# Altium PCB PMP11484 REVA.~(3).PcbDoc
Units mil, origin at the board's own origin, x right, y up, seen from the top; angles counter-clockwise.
Board outline 4950 x 3450 mil, 2 copper layers (Top Layer, Bottom Layer), stack 62 mil thick; 51 components, 24 nets, 109 pads, 5 vias.
Unrouted connection lines stored in the file: 85.
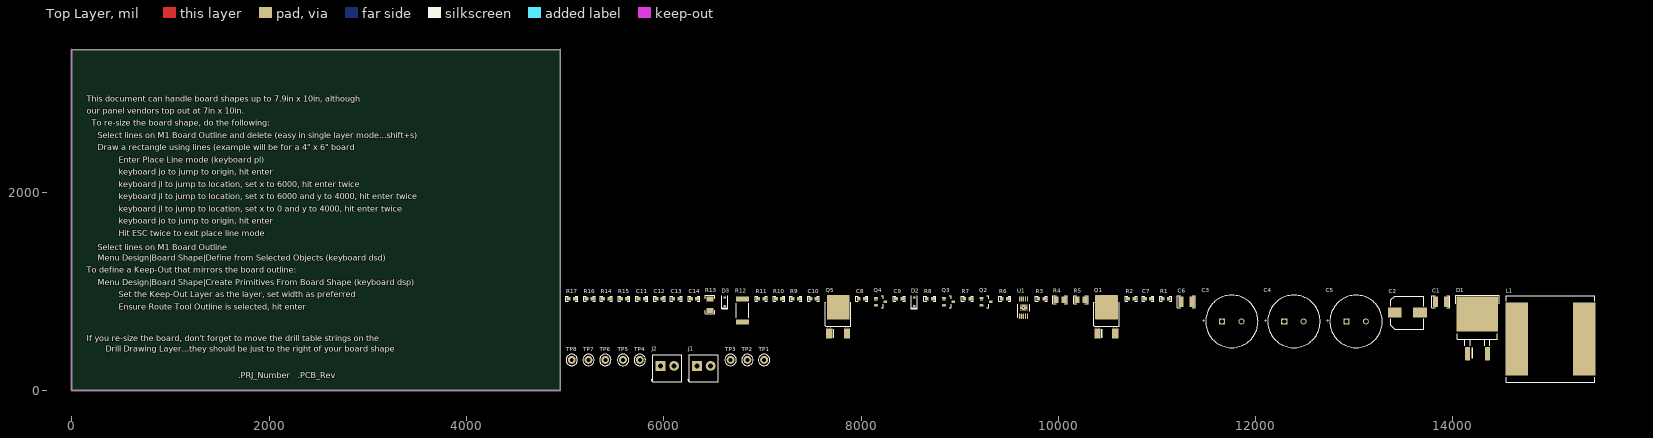
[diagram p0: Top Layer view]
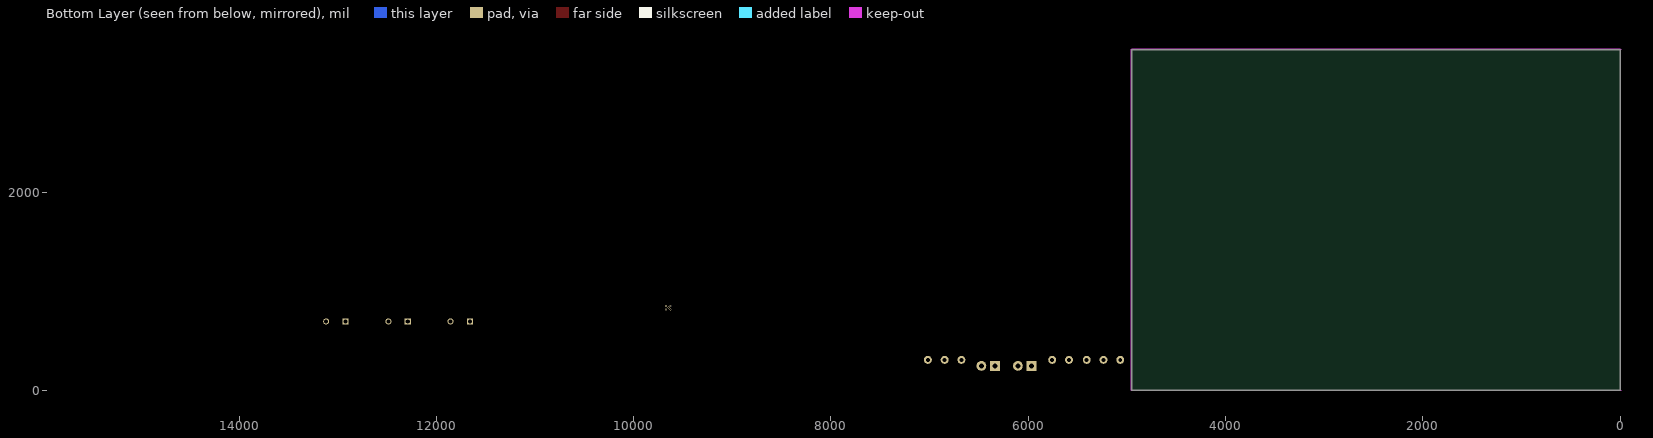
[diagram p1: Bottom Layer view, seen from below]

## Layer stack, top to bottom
Top Solder: solder mask 0.4, Solder Resist, Dk 3.5
Top Layer: signal copper 1.4
Dielectric1: core 59.2, FR-4, Dk 4.8
Bottom Layer: signal copper 1.4
Bottom Solder: solder mask 0.4, Solder Resist, Dk 3.5

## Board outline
0,0 4950,0 4950,3450 0,3450

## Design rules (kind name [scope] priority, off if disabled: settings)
AcuteAngle [All] p1: minimum=4.50000000000000E+0001 checktracksonly=FALSE
AssemblyTestPointUsage [All] p1: valid=2
Clearance Clearance_Keepouts [((IsTrack Or IsArc) And Not InPoly) And IsFree and IsKeepOut vs ((IsTrack Or IsArc) And Not InPoly) And IsFree and IsKeepOut] p1: gap=0
Clearance Clearance_BoardEdge_MountingHoles [OnCopper and InComponentClass('Mounting Holes') vs IsKeepOut] p2: gap=40
Clearance Clearance_BoardEdge_Poly [OnCopper and InPoly vs IsKeepOut] p3: gap=25
Clearance Clearance_BoardEdge [OnCopper and Not InComponentClass('Logo') and not InComponentClass('FiducialMark') and not InRegion(1000,500,4000,800) and Not IsKeepout vs IsKeepOut] p4: gap=75
Clearance Clearance_Poly [InPolygon] p5: gap=25
Clearance [All] p6: gap=7.87
ComponentClearance ComponentClearance_MountingHoles_FiducialMarks [InComponentClass('Mounting Holes') vs InComponentClass('FiducialMark')] p1: gap=50 collisioncheckmode=3 verticalgap=10 showdistances=FALSE
ComponentClearance ComponentClearance_Shunt [InComponentClass('Header') vs InComponentClass('Shunt')] p2: gap=0 collisioncheckmode=3 verticalgap=0 showdistances=FALSE
ComponentClearance ComponentClearance_Logo [InComponentClass('Logo')] p3: gap=50 collisioncheckmode=3 verticalgap=10 showdistances=FALSE
ComponentClearance ComponentClearance_ScrewToNut [(HasFootprint('NY PMS 440 0025 PH')) vs (HasFootprint('Keystone_1902C'))] p4: gap=5 collisioncheckmode=3 verticalgap=10 showdistances=FALSE
ComponentClearance ComponentClearance_MountingHoles [InComponentClass('Mounting Holes')] p5: gap=250 collisioncheckmode=3 verticalgap=100000 showdistances=FALSE
ComponentClearance ComponentClearance_SmallPassives [HasFootprint('0201*') or HasFootprint('0402*') or HasFootprint('0508') or HasFootprint('0603*') or HasFootprint('0612') or HasFootprint('0805*') or HasFootprint('0815*') or HasFootprint('0830*') or HasFootprint('1206*') or HasFootprint('1210*') or HasFootprint('1808*') or HasFootprint('1812*') or HasFootprint('1825*') or HasFootprint('2010*') or HasFootprint('2220*') or HasFootprint('2225*') or HasFootprint('2512*') or HasFootprint('2728*') or HasFootprint('3518*') vs HasFootprint('0201*') or HasFootprint('0402*') or HasFootprint('0508') or HasFootprint('0603*') or HasFootprint('0612') or HasFootprint('0805*') or HasFootprint('0815*') or HasFootprint('0830*') or HasFootprint('1206*') or HasFootprint('1210*') or HasFootprint('1808*') or HasFootprint('1812*') or HasFootprint('1825*') or HasFootprint('2010*') or HasFootprint('2220*') or HasFootprint('2225*') or HasFootprint('2512*') or HasFootprint('2728*') or HasFootprint('3518*')] p6: gap=20 collisioncheckmode=3 verticalgap=10 showdistances=FALSE
ComponentClearance ComponentClearance_THtoSMT [IsThruComponent vs IsSMTComponent] p7: gap=100 collisioncheckmode=3 verticalgap=30 showdistances=FALSE
ComponentClearance ComponentClearance_THtoTH [IsThruComponent vs IsThruComponent] p8: gap=118.11 collisioncheckmode=3 verticalgap=30 showdistances=FALSE
ComponentClearance [All] p9: gap=40 collisioncheckmode=3 verticalgap=10 showdistances=FALSE
DiffPairsRouting [All] p1: maxlimit=100 minlimit=10 mostfreqgap=10 toplayer_minwidth=15 toplayer_maxwidth=15 toplayer_prefwidth=15 bottomlayer_minwidth=15 bottomlayer_maxwidth=15 bottomlayer_prefwidth=15 maxuncoupledlength=1000
FabricationTestPointUsage TestPointUsage [All] p1: valid=2 allowmultiple=FALSE
FabricationTestpoint Testpoint [All] p1: side=3 testpointundercomponent=TRUE minsize=40 maxsize=100 preferedsize=60 minholesize=0 maxholesize=40 preferedholesize=32 testpointgrid=1 allowsidetop=TRUE allowsidebottom=TRUE usegrid=TRUE gridtolerance=0.01
FanoutControl Fanout_LCC [IsLCC] p1: bgadir=Out bgaviamode=Centered fanoutstyle=Auto fanoutdirection=Alternating viagrid=1 // Fanout_LCC (Default Rule)
FanoutControl Fanout_BGA [IsBGA] p2: bgadir=Out bgaviamode=Centered fanoutstyle=Auto fanoutdirection=Alternating viagrid=1 // Fanout_BGA (Default Rule)
FanoutControl Fanout_Default [All] p4: bgadir=Out bgaviamode=Centered fanoutstyle=Auto fanoutdirection=Alternating viagrid=1 // Fanout_Default (Default Rule)
FanoutControl Fanout_Small [(CompPinCount < 5)] p5: bgadir=Out bgaviamode=Centered fanoutstyle=Auto fanoutdirection=OutThenIn viagrid=1 // Fanout_Small (Default Rule)
HoleSize [All] p1: absolutevalues=TRUE maxlimit=251 minlimit=8 maxpercent=80.000 minpercent=20.000
MinimumAnnularRing MinimumAnnularRing_ThermalPadVias [IsVia and InAnyComponent] p1: minimumring=5.91
MinimumAnnularRing [All] p2: minimumring=9
MinimumSolderMaskSliver MinimumSolderMaskSliver_Logo [InComponentClass('Logo') vs InComponentClass('Logo')] p1: minsoldermaskwidth=0.7
MinimumSolderMaskSliver [All] p2: minsoldermaskwidth=3.94
PlaneConnect [All] p1: planeconnectstyle=Relief reliefexpansion=10 reliefentries=4 reliefconductorwidth=10 reliefairgap=10
PolygonConnect [All] p1: connectstyle=Relief reliefconductorwidth=10 reliefentries=4 polygonreliefangle="90 Angle" airgapwidth=10
RoutingVias ThermalPadVias [IsVia and InAnyComponent] p1: holewidth=7.87 width=19.68 viastyle="Through Hole" minholewidth=7.87 minwidth=19.68 maxholewidth=12.99 maxwidth=23.62
RoutingVias [All] p2: holewidth=16 width=34 viastyle="Through Hole" minholewidth=7.87 minwidth=26 maxholewidth=40 maxwidth=65
SilkToBoardRegionClearance [Not ((IsComment or IsDesignator) And (Hide <> 'False')) and not InRegion(1000,500,4000,800)] p1:
SilkToSilkClearance SilkToSilkClearance_Pb-FreeLogo [(HasFootprint('Pb-Free_Overlay_Medium') OR HasFootprint('Pb-Free_Overlay_Small')) vs (HasFootprint('Pb-Free_Overlay_Medium') OR HasFootprint('Pb-Free_Overlay_Small'))] p1: silktosilkclearance=0
SilkToSilkClearance [All] p2: silktosilkclearance=4
SilkToSolderMaskClearance SilkToComonentPadClearance [IsPad and InAnycomponent] p1: minsilkscreentomaskgap=5 clearancetoexposedcopper=TRUE
SilkToSolderMaskClearance "Silk to Solder Mask Opening" [All] p2: minsilkscreentomaskgap=4 clearancetoexposedcopper=FALSE
SolderMaskExpansion [All] p1: expansion=1.97
UnpouredPolygon [All] p1: allowunpoured=FALSE
Width [All] p1: maxlimit=100 minlimit=6 preferedwidth=10 checkconnectedcopper=TRUE
14 further rules are at their usual default settings.

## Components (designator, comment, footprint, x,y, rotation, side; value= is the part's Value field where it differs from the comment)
C1 "C3225X7R1H475M250AB" 1210 13878,896 r0 top
C2 "EEHZA1H680P" SM_RADIAL_8MM 13538,786 r0 top
C3 "UBT1K221MHD1TO" BT_1250x2500 11758,696 r0 top
C4 "UBT1K221MHD1TO" BT_1250x2500 12388,696 r0 top
C5 "UBT1K221MHD1TO" BT_1250x2500 13018,696 r0 top
C6 "GRM32ER72A225KA35L" 1210 11298,896 r0 top
C7 "C1608X7R1H104K" 0603 10908,926 r0 top
C8 "C1608X7R1H104K" 0603 8008,926 r0 top
C9 "C1608C0G2A102J" 0603 8388,926 r0 top
C10 "C1608C0G1H331J" 0603 7518,926 r0 top
C11 "C1608X7R1H104K" 0603 5778,926 r0 top
C12 "C1608C0G1H331J" 0603 5958,926 r0 top
C13 "C1608X7R1C105K" 0603 6128,926 r0 top
C14 "C1608C0G1H331J" 0603 6308,926 r0 top
D1 "NRVBB1060T4G" DDPAK 14248,616 r90 top
D2 "MMSZ5230BS-7-F" sod-323 8538,896 r90 top
D3 "MMSZ5230BS-7-F" sod-323 6618,896 r90 top
J1 "ED555/2DS" TERM_BLK_ED555-2DS 6338,246 r0 top
J2 "ED555/2DS" TERM_BLK_ED555-2DS 5968,246 r0 top
L1 "IHLP8787MZER220M5A" IHLP8787MZ 14988,516 r0 top
Q1 "IPD50N06S4L-12" DPAK 10488,706 r90 top
Q2 "MMBT2222A" SOT-23 9268,896 r0 top
Q3 "MMBT2222A" SOT-23 8888,896 r0 top
Q4 "MMBT2907A" SOT-23 8198,896 r0 top
Q5 "IPD50N06S4L-12" DPAK 7768,706 r90 top
R1 "CRCW06034R70JNEA" 0603 11088,926 r0 top
R2 "CRCW0603348KFKEA" 0603 10738,926 r0 top
R3 "CRCW0603402KFKEA" 0603 9828,926 r0 top
R4 "CRCW080520K0FKEA" 0805_HV 10018,916 r0 top
R5 "CRCW080520K0FKEA" 0805_HV 10228,916 r0 top
R6 "CRCW06030000Z0EA" 0603 9458,926 r0 top
R7 "CRCW06034R70JNEA" 0603 9078,926 r0 top
R8 "CRCW06030000Z0EA" 0603 8698,926 r0 top
R9 "CRCW06031K00FKEA" 0603 7338,926 r0 top
R10 "CRCW0603147KFKEA" 0603 7168,926 r0 top
R11 "CRCW060310K0FKEA" 0603 6988,926 r0 top
R12 "WSL25127L000FEA" 2512 6798,806 r90 top
R13 "CRCW12064R70JNEA" 1206 6468,866 r90 top
R14 "CRCW0603100KFKEA" 0603 5418,926 r0 top
R15 "CRCW060349R9FKEA" 0603 5598,926 r0 top
R16 "CRCW06032K10FKEA" 0603 5248,926 r0 top
R17 "CRCW060329R4FKEA" 0603 5068,926 r0 top
TP1 "5000" Keystone5000 7018,306 r0 top
TP2 "5000" Keystone5000 6848,306 r0 top
TP3 "5000" Keystone5000 6678,306 r0 top
TP4 "5001" Keystone5001 5758,306 r0 top
TP5 "5001" Keystone5001 5588,306 r0 top
TP6 "5000" Keystone5000 5408,306 r0 top
TP7 "5001" Keystone5001 5238,306 r0 top
TP8 "5000" Keystone5000 5068,306 r0 top
U1 "TPS40210DGQR" DGQ0010D_N 9648,836 r90 top

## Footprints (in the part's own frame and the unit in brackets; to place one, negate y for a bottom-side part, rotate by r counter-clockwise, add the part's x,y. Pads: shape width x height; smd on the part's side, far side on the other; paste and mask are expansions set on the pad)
0603 [mm] "0603 from SM-752 data"
  rect 1x0.95 smd: 1(-0.8,0) 2(0.8,0)
  silkscreen extent -1.52,-0.69 1.52,0.69, body extent -0.87,-0.47 0.87,0.47, height 1
0805_HV [mil] "0805 with 30mil clearance between pads"
  rect 50x63 smd: 1(-40,0) 2(40,0)
  silkscreen extent -74,-40 74,40, body extent -43,-29 43,29, height 57
1206 [mm] "1206 from SM-752 data"
  rect 1.3x1.85 smd: 1(-1.45,0) 2(1.45,0)
  silkscreen extent -2.4,-1.21 2.4,1.21, body extent -1.7,-0.9 1.7,0.9, height 1.35
1210 [mm] "1210 from SM-752 data"
  rect 1.3x2.7 smd: 1(-1.45,0) 2(1.45,0)
  silkscreen extent -2.32,-1.57 2.32,1.57, body extent -1.7,-1.35 1.7,1.35, height 1.35
2512 [mm] "Chip Resistor, Body 6.3x3.2mm, IPC Medium Density"
  rect 1.3x3.4 smd: 1(-2.95,0) 2(2.95,0)
  silkscreen extent -1.9,-1.6 1.9,1.6, body extent -3.22,-1.67 3.22,1.67, height 0.71
BT_1250x2500 [mm] "TH, 2-Leads, Dia 12.5mm, Lead Sapcing 5mm"
  rect 1.55x1.55 hole 1.05: 1(-2.5,0)
  round 1.55 hole 1.05: 2(2.5,0)
  silkscreen extent -6.75,-6.75 6.75,6.75, body extent -6.7,-6.74 6.73,6.74, height 27.01
DDPAK [mil] "D2-PAK, 3-Pads, Body 9.7x10.4mm (max), TO-263AB, using Vishay Silionix recommended pad sizes"
  rrect8% 135x49.49 smd: 1(-246.06,100) 3(-246.06,-100)
  rrect1% 355x420 smd paste-181.1: 4(155.51,0)
  silkscreen extent -295,-220 344,220, body extent -295,-202 324,202, height 180
DGQ0010D_N [mm] "TSSOP, 10-Leads, Body 3x3mm, Pitch 0.5mm, Thermal Pad 1.88x1.57mm, IPC Medium Density"
  rrect100% 1.35x0.3 smd: 1(-2.225,1) 2(-2.225,0.5) 3(-2.225,0) 4(-2.225,-0.5) 5(-2.225,-1) 6(2.225,-1) 7(2.225,-0.5) 8(2.225,0) 9(2.225,0.5) 10(2.225,1)
  rrect6% 1.57x1.88 smd: 11(0,0)
  silkscreen extent -2.65,-1.55 0.9,1.55, body extent -2.46,-1.5 2.46,1.5, height 1.1
DPAK [mm] "D-PAK, 3-Pads, Body 6.22x6.73mm (max), TO-252AA using nominal STEP model"
  rrect6% 2.6x1.6 smd: 1(-3.4,2.28) 3(-3.4,-2.28)
  rrect2% 6.2x5.8 smd paste-2.9: 4(3.4,0)
  silkscreen extent -4.5,-3.3 4.7,3.28, body extent -3.86,-3.29 5.84,3.29, height 2.48
IHLP8787MZ [mm] "SMD, 2-Leads, Body 22x22.48mm"
  rect 5.84x18.8 smd: 1(-8.7,0) 2(8.7,0)
  silkscreen extent -11.39,-11.15 11.39,11.15, body extent -11.39,-11.15 11.39,11.15, height 13
Keystone5000 [mil] "For Keystone 500x miniature loop terminals"
  round 80 hole 40: 1(0,0)
  silkscreen extent -58,-58 58,58, body extent -49,-49 49,49, height 182
Keystone5001 [mil] "For Keystone 500x miniature loop terminals"
  round 80 hole 40: 1(0,0)
  silkscreen extent -58,-58 58,58, body extent -49,-49 49,49, height 182
SM_RADIAL_8MM [mm] "Nichicon 8x10"
  rect 3.5x2.5 smd: 1(-3.25,0) 2(3.25,0)
  silkscreen extent -4.25,-4.25 4.25,4.25, body extent -4.26,-4.26 4.26,4.26, height 10.5
sod-323 [mm] "NXP recommended land pattern"
  rect 0.6x0.6 smd paste-0.05: 1(-1.1,0) 2(1.1,0)
  silkscreen extent -2.06,-0.86 1.53,0.86, body extent -1.3,-0.67 1.3,0.68, height 1.1
SOT-23 [mm] "SOT23, 3-Leads, Body 2.9x1.3mm, Pitch 0.95mm, Lead Span 2.5mm, IPC Medium Density"
  rrect50% 1x0.6 smd: 1(-1.2,0.95) 2(-1.2,-0.95) 3(1.2,0)
  silkscreen extent -1.63,-1.5 0.7,1.5, body extent -1.16,-1.45 1.21,1.45, height 1
TERM_BLK_ED555-2DS [mil]
  rect 100x100 hole 50: 1(0,0)
  round 100 hole 50: 2(138,0)
  silkscreen extent -93,-161 215,113, body extent -69,-150 207,106, height 323

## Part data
C1: library part C3225X7R1H335M, "CAP, CERM, 4.7uF, 50V, +/-20%, X7R, 1210"
C2: "CAP, Polymer Hybrid, 68 µF, 50 V, +/- 20%, 30 ohm, 8x10 SMD"
C3 C4 C5: library part UBT1H471MHD1TO, "CAP, AL, 220 µF, 80 V, +/- 20%, 0.180 ohm, 1.24A, AEC-Q200 Grade 1, TH"
C6: "CAP, CERM, 2.2 µF, 100 V, +/- 10%, X7R, 1210"
C7 C8 C11: "CAP, CERM, 0.1uF, 50V, +/-10%, X7R, 0603"
C9: "CAP, CERM, 1000 pF, 100 V, +/- 5%, C0G/NP0, 0603"
C10 C12 C14: "CAP, CERM, 330 pF, 50 V, +/- 5%, C0G/NP0, 0603"
C13: "CAP, CERM, 1uF, 16V, +/-10%, X7R, 0603"
D1: library part MBRB2515LT4G, "Diode, Schottky, 60V, 10A, DDPAK"
D2 D3: "Diode, Zener, 4.7 V, 200 mW, SOD-323"
J1 J2: "Terminal Block, 6A, 3.5mm Pitch, 2-Pos, TH"
L1: library part IHLP8787MZE470M51, "Inductor, Shielded, 22 µH, 16 A, 0.0106 ohm, SMD"
Q1 Q5: library part IPD50R280CE, "MOSFET, N-CH, 60 V, 0.012 Ohms, AEC-Q101, DPAK"
Q2 Q3: library part "MMBT2222A, Fairchild Semiconductor", "Transistor, NPN, 40 V, 0.15 A, SOT-23"
Q4: library part "MMBT2907A, Fairchild Semiconductor", "Transistor, PNP, 60 V, 0.8 A, SOT-23"
R1 R7: "RES, 4.7 ohm, 5%, 0.1W, 0603"
R2: "RES, 348 k, 1%, 0.1 W, 0603"
R3: "RES, 402 k, 1%, 0.1 W, 0603"
R4 R5: "RES, 20.0 k, 1%, 0.125 W, 0805"
R6 R8: "RES, 0, 5%, 0.1 W, 0603"
R9: "RES, 1.00k ohm, 1%, 0.1W, 0603"
R10: "RES, 147 k, 1%, 0.1 W, 0603"
R11: "RES, 10.0 k, 1%, 0.1 W, 0603"
R12: library part WSL25129L000FEA18, "RES, 0.007, 1%, 2 W, 2512"
R13: "RES, 4.7, 5%, 0.25 W, 1206"
R14: "RES, 100k ohm, 1%, 0.1W, 0603"
R15: "RES, 49.9 ohm, 1%, 0.1W, 0603"
R16: "RES, 2.10 k, 1%, 0.1 W, 0603"
R17: "RES, 29.4, 1%, 0.1 W, 0603"
TP1 TP2 TP3 TP6 TP8: "Test Point, Miniature, Red, TH"
TP4 TP5 TP7: "Test Point, Miniature, Black, TH"
U1: "4.5-V TO 52-V INPUT CURRENT MODE BOOST CONTROLLER, DGQ0010D"

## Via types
v1: diameter 19.68, hole 7.87, Top Layer to Bottom Layer, 5 vias

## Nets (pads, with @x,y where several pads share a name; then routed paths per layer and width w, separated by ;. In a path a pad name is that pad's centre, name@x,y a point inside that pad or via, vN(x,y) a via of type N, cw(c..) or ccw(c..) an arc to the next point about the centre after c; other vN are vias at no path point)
GND: C1.1 C2.2 C3.2 C4.2 C5.2 C6.2 C7.2 C11.2 C12.2 C13.2 C14.2 D3.2 J1.2 J2.2 Q3.2 Q4.3 R11.1 R12.1 R13.1 R17.1 TP4.1 TP5.1 TP7.1 U1.6 U1.11
  other v1: 9624.38,818.28 9671.62,818.28 9648,836 9624.38,853.72 9671.62,853.72
NetC1_2: C1.2 C2.1 J1.1 L1.1 R1.2 TP1.1
NetC7_1: C7.1 R1.1 R2.2 R4.2 R5.2 U1.10
NetC8_1: C8.1 C10.2 U1.4
NetC8_2: C8.2 R10.1
NetC9_1: C9.1 D1.1 D1.3 L1.2 Q1.4 Q5.4 TP2.1
NetC9_2: C9.2 R13.2
NetC10_1: C10.1 R10.2 R14.2 R16.2 U1.5
NetC11_1: C11.1 U1.2
NetC12_1: C12.1 R2.1 U1.1
NetC13_1: C13.1 Q2.3 U1.9
NetC14_1: C14.1 R9.2 U1.7
NetD2_1: D2.1 R3.1 R4.1
NetD2_2: D2.2 Q3.1 R11.2
NetD3_1: D3.1 Q3.3 R5.1 TP6.1 U1.3
NetQ1_1: Q1.1 R6.2
NetQ1_3: Q1.3 Q5.3 R9.1 R12.2
NetQ2_1: Q2.1 Q4.1 R7.2
NetQ2_2: Q2.2 Q4.2 R6.1 R8.1
NetQ5_1: Q5.1 R8.2
NetR7_1: R7.1 U1.8
NetR14_1: R14.1 R15.2 TP8.1
NetR16_1: R16.1 R17.2
VOUT: C3.1 C4.1 C5.1 C6.1 D1.4 J2.1 R3.2 R15.1 TP3.1

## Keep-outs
Keep-Out Layer:
  lines w10: -5,0 ccw(c0,0) 0,-5 ; -5,0 ccw(c0,0) 0,-5 ; -5,0 -5,3450 ; -5,3450 cw(c0,3450) 0,3455 ; -5,3450 cw(c0,3450) 0,3455 ; 0,-5 4950,-5 ; 0,3455 4950,3455 ; 4950,-5 ccw(c4950,0) 4955,0 ; 4950,-5 ccw(c4950,0) 4955,0 ; 4950,3455 cw(c4950,3450) 4955,3450 ; 4950,3455 cw(c4950,3450) 4955,3450 ; 4955,0 4955,3450
  text ".Layer_Name" at 577,-858.49 h60

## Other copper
Top Layer:
  text ".Layer_Name" at 577,-858.49 h60
Bottom Layer:
  text ".Layer_Name" at 577,-858.49 h60

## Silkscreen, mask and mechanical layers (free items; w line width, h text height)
Top Overlay:
  text "This document can handle board shapes up to 7.9in x 10in, although" at 150,2925 h60
  text "our panel vendors top out at 7in x 10in." at 150,2800.94 h60
  text "To re-size the board shape, do the following:" at 205,2676.88 h60
  text "Select lines on M1 Board Outline and delete (easy in single layer mode...shift+s)" at 265,2552.82 h60
  text "Draw a rectangle using lines (example will be for a 4\" x 6\" board" at 265,2428.76 h60
  text "Enter Place Line mode (keyboard pl)" at 475,2304.71 h60
  text "keyboard jo to jump to origin, hit enter" at 475,2180.65 h60
  text "keyboard jl to jump to location, set x to 6000, hit enter twice" at 475,2056.59 h60
  text "keyboard jl to jump to location, set x to 6000 and y to 4000, hit enter twice" at 475,1932.53 h60
  text "keyboard jl to jump to location, set x to 0 and y to 4000, hit enter twice" at 475,1808.47 h60
  text "keyboard jo to jump to origin, hit enter" at 475,1684.41 h60
  text "Hit ESC twice to exit place line mode" at 475,1560.35 h60
  text "Select lines on M1 Board Outline" at 265,1416.3 h60
  text "Menu Design|Board Shape|Define from Selected Objects (keyboard dsd)" at 265,1312.24 h60
  text "To define a Keep-Out that mirrors the board outline:" at 150,1188.18 h60
  text "Menu Design|Board Shape|Create Primitives From Board Shape (keyboard dsp)" at 265,1064.12 h60
  text "Set the Keep-Out Layer as the layer, set width as preferred" at 475,940.06 h60
  text "Ensure Route Tool Outline is selected, hit enter" at 475,816 h60
  text "If you re-size the board, don't forget to move the drill table strings on the" at 150,493 h60
  text "Drill Drawing Layer...they should be just to the right of your board shape" at 343,387 h60
  text ".PRJ_Number" at 1690,120 h60
  text ".PCB_Rev" at 2290,120 h60
  text ".Layer_Name" at 577,-858.49 h60
Bottom Overlay:
  text ".Layer_Name" at 577,-858.49 h60
Top Paste:
  text ".Layer_Name" at 577,-858.49 h60
Bottom Paste:
  text ".Layer_Name" at 577,-858.49 h60
Top Solder:
  text ".Layer_Name" at 577,-858.49 h60
  text ".Layer_Name" at 577,-858.49 h60
Bottom Solder:
  text ".Layer_Name" at 577,-858.49 h60
Drill Guide:
  text ".Layer_Name" at 577,-858.49 h60
M1 Board Outline:
  the board outline again, w10
  text ".Layer_Name" at 577,-858.49 h60
M2 Board Dimensions:
  rectangle: 0,-275 125,-150
  rectangle: 125,-400 500,-275
  lines w7: 0,-275 1000,-275 ; 125,-400 125,-150 ; 250,-400 250,-150 ; 500,-400 500,-150 ; 750,-400 750,-150 ; 0,-400 1000,-400 1000,-150 0,-150 0,-400
  text ".Layer_Name" at 577,-858.49 h60
M3 3D STEP Top:
  text ".Layer_Name" at 577,-858.49 h60
M4 3D STEP Bottom:
  text ".Layer_Name" at 577,-858.49 h60
M5 Assembly Top:
  lines w10: -292,-930.17 6308,-930.17 ; -292,-726.83 6310,-726.83 ; -292,-523.5 -292,-1133.5 3713,-1133.5 6310,-1133.5 6310,-523.5 -291.5,-523.5 -291.5,-1133.5 1284,-1133.5 ; 2173,-1133.5 2173,-523.5 ; 3440,-726.83 3440,-523.5 ; 4280,-726.83 4280,-523.5 ; 4902,-1140 4902,-937.17
  text "COMPONENTS MARKED 'DNP' SHOULD NOT BE POPULATED." at 1153.5,-318.5 h60
  text "ASSEMBLY VARIANT:" at 1153,-434 h60
  text ".VariantName" at 2189,-434 h60
  text "PCB VIEWED FROM TOP SIDE" at -228.5,-655.67 h60
  text "BOARD #:" at 2248,-655.67 h60
  text ".PRJ_Number" at 2793.5,-655.67 h60
  text "REV:" at 3638,-655.67 h60
  text ".PCB_Rev" at 3929.5,-655.67 h60
  text "SVN REV:" at 4476,-655.67 h60
  text ".VersionControl_RevNumber" at 4982,-655.67 h60
  text "TID #:" at 2248,-859 h60
  text ".TID" at 2793.5,-859 h60
  text "PLOT NAME =" at -228.5,-1064.34 h60
  text ".plot_File_Name" at 577,-1064.34 h60
  text "GENERATED    :" at 2250,-1064.34 h60
  text ".Print_Date" at 3119.5,-1064.34 h60
  text ".Print_Time" at 3848.5,-1064.34 h60
  text "TEXAS INSTRUMENTS" at 5113,-1064.34 h60
M6 Assembly Bottom:
  lines w10: -292.5,-727.33 6309.5,-727.33 ; -290.5,-930.67 6309.5,-930.67 ; 1115.5,-1140.5 1115.5,-937.67 ; 1737.5,-727.33 1737.5,-524 ; 2577.5,-727.33 2577.5,-524 ; 3844.5,-1134 3844.5,-524 ; 4733.5,-1134 6309,-1134 6309,-524 -292.5,-524 -292.5,-1134 2304.5,-1134 6309.5,-1134 6309.5,-524
  text "COMPONENTS MARKED 'DNP' SHOULD NOT BE POPULATED." at 6102,-318 h60
  text ".VariantName" at 5058,-434 h60
  text "ASSEMBLY VARIANT:" at 6097,-434 h60
  text ".VersionControl_RevNumber" at 1035.5,-656.17 h60
  text "SVN REV:" at 1541.5,-656.17 h60
  text ".PCB_Rev" at 2088,-656.17 h60
  text "REV:" at 2379.5,-656.17 h60
  text ".PRJ_Number" at 3224,-656.17 h60
  text "BOARD #:" at 3769.5,-656.17 h60
  text "PCB VIEWED FROM BOTTOM SIDE" at 6246,-656.17 h60
  text ".TID" at 3224,-859.5 h60
  text "TID #:" at 3769.5,-859.5 h60
  text "TEXAS INSTRUMENTS" at 904.5,-1064.84 h60
  text ".Print_Time" at 2169,-1064.84 h60
  text ".Print_Date" at 2898,-1064.84 h60
  text "GENERATED    :" at 3767.5,-1064.84 h60
  text ".plot_File_Name" at 5440.5,-1064.84 h60
  text "PLOT NAME =" at 6246,-1064.84 h60
M9 Title Sheet:
  drawing of 57 lines, arcs and shapes, not listed
  text "1" at 739.84,8036.5 h70
  text "2" at 3235.5,8036.5 h70
  text "3" at 5724.84,8036.5 h70
  text "4" at 8231.51,8036.5 h70
  text "5" at 10730.5,8036.5 h70
  text "6" at 13235.5,8036.5 h70
  text "A" at -416.5,6893.5 h70
  text "A" at 14383.5,6893.5 h70
  text "B" at -416.5,4513.5 h70
  text "B" at 14383.5,4513.5 h70
  text "C" at -416.5,2138.5 h70
  text "C" at 14383.5,2138.5 h70
  text "PROJECT TITLE:" at 11343.5,277.5 h45
  text ".PRJ_Title" at 11393.5,144.17 h70
  text "DESIGNED FOR:" at 11343.5,-23.5 h45
  text ".PRJ_Customer" at 11393.5,-163.5 h70
  text "D" at -416.5,-231.5 h70
  text "D" at 14383.5,-231.5 h70
  text "FILE NAME:" at 11343.5,-323.5 h45
  text ".PCB_File_Name_No_Path" at 11393.5,-443.5 h70
  text "Texas Instruments (TI) and/or its licensors do not warrant the accuracy or completeness of this specification" at 6374,-605.34 h45
  text "ENGINEER:" at 11343.5,-613.5 h45
  text "LAYOUT BY:" at 12848.5,-613.5 h45
  text "or any information contained therein. TI and/or its licensors do not warrant that this design will meet" at 6329.01,-718 h45
  text ".PRJ_Engineer" at 11393.5,-768.49 h70
  text ".PCB_Layout" at 12899,-768.49 h70
  text "the specifications, will be suitable for your application or fit for any particular purpose, or will operate in" at 6329.01,-830.67 h45
  text ".Layer_Name" at 577,-858.49 h60
  text "ALTIUM DESIGNER VERSION:" at 12848.5,-923.5 h45
  text "an implementation. TI and/or its licensors do not warrant that the design is production worthy. You should" at 6329.01,-943.33 h45
  text "completely validate and test your design implementation to confirm the system functionality for your application." at 6374,-1056 h45
  text ".print_Scale" at 11393.5,-1056.83 h70
  text ".Application_BuildNumber" at 12899,-1056.83 h70
  text "1" at 739.84,-1263.5 h70
  text "2" at 3235.5,-1263.5 h70
  text "3" at 5724.84,-1263.5 h70
  text "4" at 8231.51,-1263.5 h70
  text "5" at 10730.5,-1263.5 h70
  text "6" at 13235.5,-1263.5 h70
M10 Fab Notes:
  drawing of 189 lines, arcs and shapes, not listed
  text "DESIGN INFORMATION" at 12381.02,6028 h60
  text "MIN. TRACK WIDTH:" at 11736.46,5848 h60
  text "8" at 12832.7,5848 h60
  text "MIL" at 12987.46,5848 h60
  text "MIN. CLEARANCE:" at 11736.46,5716 h60
  text "0.2" at 12772.7,5716 h60
  text "mm" at 12987.46,5716 h60
  text "MIN. VIA PAD SIZE:" at 11736.46,5584 h60
  text "24" at 12802.71,5584 h60
  text "MIL" at 12987.46,5584 h60
  text "0.05mm (2MIL)" at 12431.46,5442.29 h60
  text "MINIMUM ANNULAR RING" at 11407.23,5438 h60
  text "EXTERNAL" at 13139.46,5438 h60
  text "PER" at 11607.23,5320 h60
  text "IPC-D-275 CLASS 2 LEVEL C" at 11827.23,5320 h60
  text "MIL, HOLES" at 13315.46,5207.71 h60
  text "+/-" at 12923,5207 h60
  text "+/-" at 13777,5207 h60
  text "REGISTRATION TOLERANCES:" at 11407.23,5202 h60
  text "METAL" at 12607,5202 h60
  text "5" at 13183.2,5202 h60
  text "3" at 14016.2,5202 h60
  text "MIL" at 14132.46,5202 h60
  text "+/-" at 13777,5089 h60
  text "HOLE SIZE TOLERANCE (UNLESS OTHERWISE SPECIFIED):" at 11407.23,5084 h60
  text "3" at 14016.2,5084 h60
  text "MIL" at 14132.46,5084 h60
  text "MATERIAL:" at 11332.46,4874.54 h60
  text "FR-4 High Tg" at 12318.9,4734.21 h60
  text "FR-408" at 11753.46,4725.64 h60
  text "OTHER" at 13241.46,4725.64 h60
  text "X" at 12164,4722 h60
  text "62 MIL (1.6mm) +/-10%" at 12073.56,4562.92 h60
  text "THICKNESS:" at 11407.23,4558.64 h60
  text "X" at 11945.4,4558.64 h60
  text "OTHER" at 13358.46,4558.64 h60
  text "TOLERANCE:" at 11407.23,4400.64 h60
  text "X" at 12246.53,4400.64 h60
  text "ANSI IPC-6012 TYPE 3 CLASS 2" at 12433.48,4400.64 h60
  text "OTHER +/-" at 12433.46,4244.64 h60
  text "BOW & TWIST:" at 11407.23,4087.64 h60
  text "X" at 12246.53,4087.64 h60
  text "ANSI IPC-6012 TYPE 3 CLASS 2" at 12433.48,4087.64 h60
  text "OTHER +/-" at 12433.46,3929.13 h60
  text "DRILLING:" at 11332.46,3790.64 h60
  text "REFERENCE:" at 11407.23,3673.64 h60
  text "X" at 12055.46,3673.64 h60
  text "AS SHOWN" at 12242.46,3673.64 h60
  text "X" at 12956.46,3673.64 h60
  text "NC_DRILL FILES" at 13093.46,3673.64 h60
  text "PTH MIN COPPER THICKNESS:" at 11407.23,3515.64 h60
  text "X" at 12757.46,3515.64 h60
  text "1MIL" at 12894.46,3515.64 h60
  text "OTHER" at 13391.46,3515.64 h60
  text "BOARD FINISH:" at 11332.46,3356.64 h60
  text "SILKSCREEN:" at 11487.68,3238.64 h60
  text "X" at 12436.46,3238.64 h60
  text "TOP" at 12562.46,3238.64 h60
  text "X" at 12946.46,3238.64 h60
  text "BOTTOM" at 13073.46,3238.64 h60
  text "SILKSCREEN COLOR:" at 11487.68,3071.64 h60
  text "X" at 12435.42,3071.64 h60
  text "WHITE" at 12562.46,3071.64 h60
  text "OTHER" at 13073.46,3071.64 h60
  text "X" at 12566.42,2912.44 h60
  text "GREEN" at 12693.46,2912.44 h60
  text "OTHER" at 13311.46,2912.44 h60
  text "SOLDER RESIST COLOR:" at 11487.68,2901.64 h60
  text "X" at 12566.42,2742.44 h60
  text "MATTE" at 12693.46,2742.44 h60
  text "SEMI-GLOSS" at 13311,2741.8 h60
  text "IMMERSION GOLD (ENIG)" at 12393.46,2553.92 h60
  text "ENEPIG" at 13731,2550.64 h60
  text "SURFACE FINISH:" at 11332.46,2549.64 h60
  text "X" at 12206.51,2549.64 h60
  text "IMM. TIN/SILVER OR EQUIV" at 11662,2392.64 h60
  text "OTHER" at 13093.46,2392.64 h60
  text "ARRAY/PANEL:" at 11332.46,2213.64 h60
  text "CUT AND TRIM PER M1 BOARD OUTLINE" at 12393.46,2209.35 h60
  text "N.C. ROUTE" at 12393.46,2057.64 h60
  text "X" at 13072.46,2057.64 h60
  text "V. SCORE" at 13259.46,2057.64 h60
  text "CERTIFICATION:" at 11332.46,1920.64 h60
  text "MATERIALS AND WORKMANSHIP FOR ALL PCBS" at 12057.46,1920.64 h60
  text "TO MEET OR EXCEED THE REQUIREMENTS OF:" at 12057.46,1822.64 h60
  text "X" at 11683.96,1686.13 h60
  text "ANSI IPC-A-600F CLASS ->" at 11822.96,1686.13 h60
  text "X" at 13462.02,1686.13 h60
  text "2" at 13580.96,1686.14 h60
  text "1" at 13265.96,1684.64 h60
  text "3" at 13934.96,1684.64 h60
  text "X" at 11686.02,1526.64 h60
  text "UL 94V-0" at 11822.96,1526.64 h60
  text "X" at 12498.02,1526.64 h60
  text "RoHS" at 12634.96,1526.64 h60
  text "OTHER" at 13279.36,1526.64 h60
  text "PER ORDER" at 13676.42,1526.64 h60
  text "ADDITIONAL REQUIREMENTS:" at 11332.46,1385.64 h60
  text "MICROSECTION:" at 11407.23,1270.64 h60
  text "YES" at 12312.96,1270.64 h60
  text "REQUIRED" at 13174.46,1114.49 h60
  text "BARE BOARD ELEC. TEST:" at 11407.23,1111.64 h60
  text "NONE" at 12712.96,1111.64 h60
  text "X" at 13047.46,1111.64 h60
  text "PER ORDER" at 13766.46,1111.64 h60
  text "MANUFACTURER'S UL:" at 11407.23,954.64 h60
  text "RAIL" at 12572.96,950.35 h60
  text "METAL" at 13064.77,950.35 h60
  text "X" at 13440,950 h60
  text "SILK" at 13576.46,950.35 h60
  text ".Layer_Name" at 577,-858.49 h60
M11 Gerber Information:
  lines w10: -292,-930.17 6308,-930.17 ; -292,-726.83 6310,-726.83 ; -292,-523.5 -292,-1133.5 3713,-1133.5 6310,-1133.5 6310,-523.5 -291.5,-523.5 -291.5,-1133.5 1284,-1133.5 ; 2173,-1133.5 2173,-523.5 ; 3440,-726.83 3440,-523.5 ; 4280,-726.83 4280,-523.5 ; 4902,-1140 4902,-937.17
  text "ALL ARTWORK VIEWED FROM TOP SIDE" at -228.5,-655.67 h60
  text "BOARD #:" at 2248,-655.67 h60
  text ".PRJ_Number" at 2793.5,-655.67 h60
  text "REV:" at 3638,-655.67 h60
  text ".PCB_Rev" at 3929.5,-655.67 h60
  text "SVN REV:" at 4476,-655.67 h60
  text ".VersionControl_RevNumber" at 4982,-655.67 h60
  text "LAYER NAME =" at -228.5,-858.49 h60
  text "TID #:" at 2248,-859 h60
  text ".TID" at 2793.5,-859 h60
  text "PLOT NAME =" at -228.5,-1064.34 h60
  text ".plot_File_Name" at 577,-1064.34 h60
  text "GENERATED    :" at 2250,-1064.34 h60
  text ".Print_Date" at 3119.5,-1064.34 h60
  text ".Print_Time" at 3848.5,-1064.34 h60
  text "TEXAS INSTRUMENTS" at 5113,-1064.34 h60
M12 Stackup:
  drawing of 191 lines, arcs and shapes, not listed
  text "Layer" at 9790.58,7830 h60
  text "Name" at 10200.49,7830 h60
  text "Material" at 11130.23,7830 h60
  text "Thickness" at 11990,7830 h60
  text "Constant" at 12639.84,7830 h60
  text "Board Layer Stack" at 13209.7,7830 h60
  text "1" at 9790.58,7710 h60
  text "Top Overlay" at 10200.49,7710 h60
  text "2" at 9790.58,7590 h60
  text "Top Solder" at 10200.49,7590 h60
  text "Solder Resist" at 11130.23,7590 h60
  text "0.40mil" at 11990,7590 h60
  text "3.5" at 12639.84,7590 h60
  text "3" at 9790.58,7470 h60
  text "Top Layer" at 10200.49,7470 h60
  text "Copper" at 11130.23,7470 h60
  text "1.40mil" at 11990,7470 h60
  text "4" at 9790.58,7350 h60
  text "Dielectric1" at 10200.49,7350 h60
  text "FR-4" at 11130.23,7350 h60
  text "59.20mil" at 11990,7350 h60
  text "4.8" at 12639.84,7350 h60
  text "5" at 9790.58,7230 h60
  text "Bottom Layer" at 10200.49,7230 h60
  text "Copper" at 11130.23,7230 h60
  text "1.40mil" at 11990,7230 h60
  text "6" at 9790.58,7110 h60
  text "Bottom Solder" at 10200.49,7110 h60
  text "Solder Resist" at 11130.23,7110 h60
  text "0.40mil" at 11990,7110 h60
  text "3.5" at 12639.84,7110 h60
  text "7" at 9790.58,6990 h60
  text "Bottom Overlay" at 10200.49,6990 h60
  text ".Layer_Name" at 577,-858.49 h60
M13 Component Bodies Top:
  text ".Layer_Name" at 577,-858.49 h60
M14 Component Bodies Bottom:
  text ".Layer_Name" at 577,-858.49 h60
M15 Courtyards Top:
  text ".Layer_Name" at 577,-858.49 h60
M16 Courtyards Bottom:
  text ".Layer_Name" at 577,-858.49 h60
Drill Drawing:
  circle w1: c5572.72,3221.04 r24.89
  lines w1: 5547.83,2748.2 5572.72,2760.64 5597.6,2748.2 5585.16,2773.08 5597.6,2797.97 5572.72,2785.53 5547.83,2797.97 5560.27,2773.08 5547.83,2748.2 ; 5547.83,2947.29 5597.6,2947.29 5572.72,2897.52 5547.83,2947.29 ; 5547.83,3059.28 5560.27,3059.28 5572.72,3046.84 5585.16,3059.28 5597.6,3059.28 5585.16,3071.72 5597.6,3084.17 5585.16,3084.17 5572.72,3096.61 5560.27,3084.17 5547.83,3084.17 5560.27,3071.72 5547.83,3059.28
  lines w12: 5480,2703.4 7598.02,2703.4 ; 5480,3300.68 7598.02,3300.68 ; 5850.36,2554.08 5850.36,3450 ; 6207.36,2554.08 6207.36,3450 ; 6868.93,2554.08 6868.93,3450 ; 7153.07,2554.08 7153.07,3450 ; 5480,2554.08 7598.02,2554.08 7598.02,3450 5480,3450 5480,2554.08
  text "Symbol" at 5569.59,3345.48 h72
  text "Quantity" at 5895.16,3345.48 h72
  text "Finished Hole Size" at 6252.16,3345.48 h72
  text "Plated" at 6913.72,3345.48 h72
  text "Hole Type" at 7197.86,3345.48 h72
  text "5" at 5895.16,3196.16 h60
  text "7.87mil (0.200mm)" at 6252.16,3196.16 h60
  text "PTH" at 6913.72,3196.16 h60
  text "Round" at 7197.86,3196.16 h60
  text "8" at 5895.16,3046.84 h60
  text "40.00mil (1.016mm)" at 6252.16,3046.84 h60
  text "PTH" at 6913.72,3046.84 h60
  text "Round" at 7197.86,3046.84 h60
  text "6" at 5895.16,2897.52 h60
  text "41.34mil (1.050mm)" at 6252.16,2897.52 h60
  text "PTH" at 6913.72,2897.52 h60
  text "Round" at 7197.86,2897.52 h60
  text "4" at 5895.16,2748.2 h60
  text "50.00mil (1.270mm)" at 6252.16,2748.2 h60
  text "PTH" at 6913.72,2748.2 h60
  text "Round" at 7197.86,2748.2 h60
  text "23 Total" at 5895.16,2598.88 h60
  text ".Layer_Name" at 577,-858.49 h60

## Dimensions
0,-400 to 1000,-400 on M2 Board Dimensions
0,0 to 0,3450 on M2 Board Dimensions
0,0 to 4950,0 on M2 Board Dimensions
